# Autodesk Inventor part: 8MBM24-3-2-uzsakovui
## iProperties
Created: 2010-09
Part Number: 8MBM24-3-2-uzsakovui
Document SubType Name: Modeling
Designer: Darius
Author: Darius
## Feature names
1. Base1
